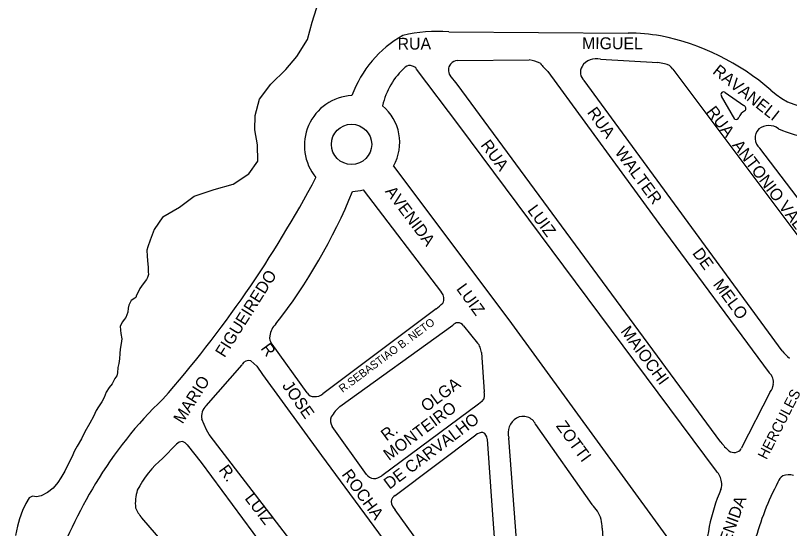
# Model space of a CAD drawing. Extents: x 325709 to 364434, y 7573432 to 7597073.
# Drawn here: x 338406.9 to 338798.1, y 7585122.9 to 7585382.2 of the extents above; entities that cross this region are included whole.
import ezdxf

# ---------------------------------------------------------------- set-up
doc = ezdxf.new("R2010")
doc.units = 0
for name, color, linetype in [('EDIFOBRAEXIS', 7, 'Continuous'), ('LOGRADOURO', 7, 'Continuous'), ('LOGRADOURO_TEXTO', 7, 'Continuous')]:
    doc.layers.add(name, color=color, linetype=linetype)

msp = doc.modelspace()

# ---------------------------------------------------------------- linework, layer by layer
at = {"layer": 'EDIFOBRAEXIS'}
for p, q in [((338765.65, 7585343.3), (338775.08, 7585336.77)), ((338770.5, 7585329.89), (338763.75, 7585341.46))]:
    msp.add_line(p, q, dxfattribs=at)
for points in [[(338481.39, 7585280.5), (338481.39, 7585280.5), (338481.39, 7585280.5), (338481.39, 7585280.5), (338481.39, 7585280.5), (338481.39, 7585280.5), (338489.69, 7585285.42), (338489.69, 7585285.42), (338489.69, 7585285.42), (338489.69, 7585285.42), (338497.23, 7585290.93), (338497.23, 7585290.93), (338497.23, 7585290.93), (338507.36, 7585294.32), (338507.36, 7585294.32), (338507.36, 7585294.32), (338516.84, 7585296.96), (338516.84, 7585296.96), (338524.79, 7585302.14), (338524.79, 7585302.14), (338529.31, 7585308.65), (338529.31, 7585308.65), (338529.17, 7585316.95), (338529.17, 7585316.95), (338527.78, 7585324.38), (338527.78, 7585324.38), (338527.96, 7585331.77), (338530.17, 7585339.95), (338530.17, 7585339.95), (338535.89, 7585347.58), (338535.89, 7585347.58), (338543.53, 7585354.9), (338543.53, 7585354.9), (338549.02, 7585361.54), (338549.02, 7585361.54), (338554.5, 7585370.1), (338554.5, 7585370.1), (338554.5, 7585370.1), (338554.5, 7585370.1), (338554.5, 7585370.1), (338556.81, 7585378.91), (338556.81, 7585378.91), (338560.25, 7585389.52)], [(338481.39, 7585280.5), (338476.91, 7585274), (338474.98, 7585268.62), (338473.69, 7585265.31), (338473.24, 7585263.65), (338473.36, 7585260.64), (338473.52, 7585258.45), (338474, 7585254.95), (338474.01, 7585252.76), (338474.04, 7585251.36), (338473.67, 7585249.9), (338473.06, 7585248.83), (338471.84, 7585247.21), (338470.65, 7585245.52), (338469.77, 7585244.3), (338468.78, 7585242.05), (338468.02, 7585240.87), (338467.7, 7585239.74), (338467.24, 7585239.33), (338465.38, 7585238.2), (338464.17, 7585235.9), (338463.87, 7585234.24), (338463.7, 7585232.22), (338462.62, 7585229.59), (338461.86, 7585228.57), (338460.92, 7585227.47), (338459.79, 7585225.27), (338460, 7585223.28), (338460.16, 7585221.44), (338460.58, 7585218.87), (338460.24, 7585216.39), (338459.84, 7585213.63), (338459.68, 7585211.36), (338459.51, 7585208.68), (338459.04, 7585206.38), (338458.64, 7585204.39), (338458.4, 7585201.56), (338458.02, 7585200.15), (338457.01, 7585198.82), (338455.82, 7585196.14), (338454.28, 7585194.17), (338452.68, 7585191.84), (338451.73, 7585189.13), (338450.44, 7585186.95), (338448.84, 7585184.44), (338447.63, 7585182.55), (338446.29, 7585179.51), (338444.42, 7585176.16), (338441.99, 7585171.81), (338440.17, 7585168.33), (338438.02, 7585164.59), (338436.71, 7585162.29), (338435.35, 7585158.94), (338433.35, 7585155.08), (338431.86, 7585151.94), (338429.86, 7585148.53), (338428.34, 7585146.28), (338425.94, 7585143.41), (338423.09, 7585141.13), (338419.88, 7585139.4), (338417.54, 7585138.9), (338416.47, 7585139.18), (338415.55, 7585139.28), (338413.84, 7585138.45), (338412.05, 7585135.64), (338410.43, 7585132.08), (338408.9, 7585127.84), (338407.82, 7585124.06), (338406.87, 7585119.41)]]:
    msp.add_lwpolyline(points, dxfattribs=at)
msp.add_circle((338576.73, 7585317.1), 10.18, dxfattribs=at)
for centre, radius, start, end in [((338764.79, 7585342.29), 1.33, 49.7996, 218.4609), ((338774.32, 7585335.25), 1.71, 315.2437, 63.4899), ((338778.26, 7585328.4), 6.27, 115.8242, 158.0595), ((338771.21, 7585330.91), 1.25, 235.2553, 352.2022)]:
    msp.add_arc(centre, radius, start, end, dxfattribs=at)
at = {"layer": 'LOGRADOURO'}
for p, q in [((338625.85, 7585373.99), (338716.56, 7585373.34)), ((338630.31, 7585359.42), (338666.5, 7585359.82)), ((338702.53, 7585360.12), (338731.52, 7585358.44)), ((338739.14, 7585355.08), (338825.69, 7585239.53)), ((338794.38, 7585212.83), (338694.3, 7585349.35)), ((338835.97, 7585245.54), (338783.15, 7585315.15)), ((338582.55, 7585294.08), (338622.24, 7585242.17)), ((338619.49, 7585234.06), (338562.24, 7585191.07)), ((338570.89, 7585184.63), (338627.98, 7585225.79)), ((338633.29, 7585225.43), (338640.47, 7585216.63)), ((338554.28, 7585191.48), (338536.53, 7585216.13)), ((338642.35, 7585211.83), (338643.81, 7585192.03)), ((338503.25, 7585185.01), (338521.38, 7585205.76)), ((338788.39, 7585192), (338773.72, 7585163.31)), ((338669.78, 7585175.5), (338698.25, 7585135.01)), ((338584.27, 7585150.29), (338566.92, 7585174.51)), ((338598.85, 7585139.67), (338639.61, 7585170.31)), ((338481.39, 7585158.42), (338488.2, 7585165.57)), ((338481.39, 7585116), (338470.7, 7585128.32))]:
    msp.add_line(p, q, dxfattribs=at)
for points in [[(338761.28, 7585151.85), (338631, 7585326.75), (338609.55, 7585355.19)], [(338763.41, 7585166.54), (338630.14, 7585347.56), (338626.52, 7585351.93)], [(338675.93, 7585353.95), (338732.08, 7585277.16), (338787.85, 7585201.57)], [(338598.02, 7585306.17), (338656.25, 7585228.47), (338746.89, 7585103.94)], [(338525.78, 7585207.71), (338528.83, 7585205.07), (338531.71, 7585200.75), (338561.52, 7585159.9), (338592.76, 7585117.61), (338629.3, 7585067.63), (338647.09, 7585041.2)], [(338642.67, 7585187.15), (338640.95, 7585185.86), (338592.1, 7585149.61)], [(338647.09, 7585041.2), (338607.19, 7585012.37), (338605.26, 7585024.38), (338601.9, 7585037.84), (338598.05, 7585047.45), (338587.48, 7585062.83), (338509.12, 7585164.71), (338504.79, 7585170.47), (338503.35, 7585172.88), (338501.08, 7585178.15)], [(338645.25, 7585168.19), (338647.83, 7585132.18), (338651.77, 7585077.49), (338651.98, 7585074.42)], [(338671.37, 7585001.91), (338662.75, 7585081.54), (338656.23, 7585168.64)], [(338493.62, 7585165.28), (338500.78, 7585156.31), (338537.36, 7585106.72), (338578.83, 7585051.17)], [(338643.86, 7585070.24), (338620.85, 7585101.79), (338598.83, 7585132.31)], [(338703.35, 7585123.08), (338708.91, 7585039.74), (338713.71, 7585001.91)]]:
    msp.add_lwpolyline(points, dxfattribs=at)
for centre, radius, start, end in [((338631.67, 7585321.46), 58.44, 119.7736, 159.6626), ((338620.35, 7585294.87), 79.31, 86.0215, 102.8924), ((338716.39, 7585276.59), 96.75, 80.177, 89.901), ((338709.32, 7585253.41), 120.83, 48.9318, 78.7497), ((338630.34, 7585354.96), 4.46, 90.3674, 142.0937), ((338664.47, 7585343.3), 16.64, 62.5917, 83.0196), ((338700.29, 7585352.08), 8.35, 74.4434, 147.7448), ((338630.38, 7585327.48), 39.1, 132.7896, 166.4646), ((338606.07, 7585353.17), 3.76, 68.0469, 126.8807), ((338606.89, 7585353.63), 3.09, 30.4242, 79.0282), ((338630.24, 7585354.63), 4.59, 138.0447, 215.927), ((338695.53, 7585375.79), 29.34, 217.1441, 228.0965), ((338698.19, 7585353.6), 5.77, 149.4248, 227.5298), ((338728.33, 7585332.23), 26.4, 75.4579, 83.0511), ((338734.33, 7585352.24), 5.59, 30.6429, 83.5773), ((338812.05, 7585369.36), 34.1, 226.7844, 316.7545), ((338578.19, 7585316.53), 25.28, 92.9918, 219.7685), ((338576.86, 7585317.99), 24.24, 330.7999, 50.2586), ((338787.26, 7585320.3), 6.59, 135.4691, 231.4303), ((338787.63, 7585318.15), 8.47, 54.2211, 126.7886), ((338814.62, 7585373.09), 52.88, 245.3689, 281.4869), ((338041.39, 7585575), 585.75, 318.69208, 332.03902), ((338315.68, 7585400.13), 282.56, 322.0523, 337.7959), ((338566.39, 7585390.8), 98.06, 276.3842, 279.4874), ((338618.52, 7585239.06), 4.86, 333.8069, 39.8976), ((338607.57, 7585251.63), 21.23, 304.1477, 316.1303), ((338545.85, 7585218.73), 10.61, 133.8902, 171.4593), ((338630.8, 7585223.12), 3.88, 96.5449, 136.5824), ((338630.6, 7585223.86), 3.12, 30.2004, 94.3205), ((338540.22, 7585219.41), 4.94, 169.5685, 221.5843), ((338637.11, 7585213.22), 4.79, 17.1639, 45.3987), ((338627.72, 7585209.89), 14.75, 7.5738, 18.7893), ((338807.44, 7585222.2), 16.07, 215.647, 234.4735), ((338524.88, 7585203.8), 4.02, 77.0704, 150.6684), ((338783.74, 7585196.85), 6.26, 350.5547, 48.9636), ((338782.31, 7585196.66), 7.66, 322.5792, 353.7317), ((338557.39, 7585193.13), 3.53, 207.9213, 277.332), ((338558.33, 7585195.57), 5.96, 265.29, 310.9834), ((338636.36, 7585190.63), 7.58, 346.5929, 10.6546), ((338620.25, 7585042.52), 201.36, 133.597, 149.1846), ((338639.16, 7585190.51), 4.86, 316.2851, 340.3092), ((338508.5, 7585179.57), 7.56, 133.9845, 190.7998), ((338583.65, 7585169.23), 19.99, 129.6566, 149.5476), ((338571.54, 7585177.45), 5.47, 159.457, 212.434), ((338663.5, 7585172.85), 6.81, 22.8113, 119.5059), ((338664.45, 7585171.29), 8.64, 119.8685, 197.8624), ((338643.35, 7585165.32), 6.24, 91.7878, 126.7895), ((338641.52, 7585168.2), 3.73, 359.8611, 64.0694), ((338491.09, 7585162.98), 3.88, 85.8492, 138.0804), ((338490, 7585162.49), 4.57, 37.6829, 72.59), ((338786.95, 7585184.39), 29.54, 217.1593, 228.6979), ((338770.04, 7585165.83), 4.47, 234.5775, 325.5412), ((338511.52, 7585121.01), 48.03, 128.8414, 153.7121), ((338753.17, 7585144.77), 10.77, 9.7582, 41.1444), ((338588.68, 7585153.7), 5.58, 217.7106, 260.9628), ((338587.63, 7585155.94), 7.76, 271.2698, 305.1924), ((338797.38, 7585144.96), 5.31, 119.9504, 164.6469), ((338797.72, 7585141.24), 8.85, 74.4475, 109.7553), ((338723.02, 7584983.01), 320.12, 149.4611, 167.3402), ((338758.07, 7585145.13), 5.9, 335.9287, 14.3554), ((338916.44, 7585080.75), 140.46, 152.1473, 165.2228), ((338489.29, 7585135.75), 21.84, 162.588, 186.0937), ((338847.48, 7585105.93), 91.73, 156.353, 181.0244), ((338600.79, 7585136.07), 4.09, 118.2483, 173.0885), ((338603.84, 7585137.43), 7.16, 186.9771, 225.6032), ((338485.43, 7585140.84), 19.33, 202.5341, 220.3442), ((338678.35, 7585115.66), 27.76, 35.3102, 44.2121), ((338688.49, 7585123.66), 14.88, 357.7739, 32.7336)]:
    msp.add_arc(centre, radius, start, end, dxfattribs=at)

# ---------------------------------------------------------------- texts
at = {"layer": 'LOGRADOURO_TEXTO'}
for s, height, rotation, p in [('RUA', 6, 0.4941, (338600.03, 7585364.93)), ('MIGUEL', 6, 359.6857, (338693.2, 7585365.27)), ('RAVANELI', 6, 321.7239, (338758.81, 7585353.24)), ('RUA', 6, 306.246, (338695.56, 7585333.22)), ('RUA', 6, 307.1913, (338755.77, 7585333.61)), ('RUA', 6, 306.3619, (338641.71, 7585316.69)), ('WALTER', 6, 306.246, (338709.53, 7585313.15)), ('ANTONIO VALDO DE MORÃES', 6, 307.1913, (338768.86, 7585316.62)), ('AVENIDA', 6, 306.8476, (338593.46, 7585293.27)), ('LUIZ', 6, 306.3619, (338665.35, 7585283.78)), ('DE', 6, 306.246, (338748.75, 7585262.07)), ('MARIO      FIGUEIREDO', 6, 57.7018, (338491.32, 7585175.45)), ('LUIZ', 6, 306.0502, (338629.43, 7585244.05)), ('MELO', 6, 306.246, (338759.2, 7585246.32)), ('R.SEBASTIAO B. NETO', 4, 36.5828, (338572.17, 7585191.48)), ('MAIOCHI', 6, 306.3619, (338712.46, 7585222.6)), ('R', 6, 306.1177, (338530.55, 7585213.95)), ('JOSE', 6, 304.9011, (338541.42, 7585195.06)), ('OLGA', 6, 36.5828, (338614.53, 7585181.59)), ('HERCULES', 5.269, 62.931, (338786.47, 7585157.44)), ('MONTEIRO', 6, 36.5828, (338595.65, 7585157.01)), ('DE CARVALHO', 6, 36.9367, (338595.85, 7585142.47)), ('ZOTTI', 6, 306.0502, (338679.87, 7585174.7)), ('R.', 6, 36.5828, (338594.36, 7585166.94)), ('R.', 6, 306.2742, (338509.34, 7585152.46)), ('ROCHA', 6, 306.1684, (338571.47, 7585150.2)), ('LUIZ', 6, 307.5659, (338522.47, 7585138.09)), ('AVENIDA', 6, 69.8213, (338764.27, 7585104.95))]:
    msp.add_text(s, height=height, rotation=rotation, dxfattribs=at).set_placement(p)

doc.saveas('drawing.dxf')
